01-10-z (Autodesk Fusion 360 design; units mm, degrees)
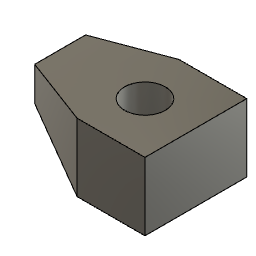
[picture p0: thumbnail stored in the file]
sketch "スケッチ1" plane through (0, 0, 0) normal (0, 0, 1) x axis (1, 0, 0)
  line L1 (-40, 0) -> (0, 0)
  line L2 (-40, 20) -> (-40, 0)
  line L3 (0, 20) -> (-40, 20)
  line L4 (0, 0) -> (0, 20)
  point P1 (0, 0)
  point P2 (0, 0)
  point P5 (0, 20)
  point P4 (-40, 20)
  horizontal L1
  vertical L2
  horizontal L3
  vertical L4
  coincident P1 P2
  dimension "d1" distance P2 P5 = 20
  dimension "d2" distance P4 P5 = 40
extrude "押し出し1" new body sketch "スケッチ1" distance 30
sketch "スケッチ2" plane through (0, 20, 0) normal (0, 1, 0) x axis (-1, 0, 0)
  line L1 (40, 15) -> (40, -15)
  line L2 (0, 15) -> (40, 15)
  line L3 (0, -15) -> (0, 15)
  line L4 (40, -15) -> (0, -15)
  line L5 (0, -15) -> (20, -15)
  line L6 (0, 15) -> (0, -15)
  line L7 (40, -7.5) -> (40, 7.5)
  line L8 (20, -15) -> (40, -7.5)
  line L9 (20, 15) -> (0, 15)
  line L10 (40, 7.5) -> (20, 15)
  point P6 (20, -15)
  point P7 (0, -15)
  point P9 (40, 7.5)
  point P10 (40, -7.5)
  parallel L4 L5
  perpendicular L4 L6
  perpendicular L2 L7
  perpendicular L6 L9
  equal L8 L10
  equal L5 L9
  collinear L4 L5
  collinear L3 L6
  collinear L2 L9
  collinear L1 L7
  dimension "d5" distance P6 P7 = 20
  dimension "d6" distance P9 P10 = 15
extrude "押し出し2" sketch "スケッチ2" no distance stored
sketch "スケッチ3" plane through (0, 0, 0) normal (0, 0, 1) x axis (1, 0, 0)
  line L1 (-20, 0) -> (-40, 10)
  line L2 (-40, 0) -> (-20, 0)
  line L3 (-40, 10) -> (-40, 0)
  line L4 (-20, 0) -> (-40, 0)
  line L5 (-40, 0) -> (-40, 20)
  line L6 (-40, 20) -> (-20, 20)
  line L7 (0, 20) -> (0, 0)
  point P2 (-40, 10)
  point P3 (-20, 0)
  horizontal L2
  collinear L2 L4
  collinear L3 L5
  dimension "d8" distance P2 L6 = 10
  dimension "d9" distance P3 L7 = 20
extrude "押し出し3" cut sketch "スケッチ3" profile of L1 L2 L3 L4 L5 no distance stored
sketch "スケッチ4" plane through (0, 20, 0) normal (0, 1, 0) x axis (-1, 0, 0)
  line L1 (40, -7.5) -> (20, -15)
  line L2 (40, 7.5) -> (40, -7.5)
  line L3 (20, 15) -> (40, 7.5)
  line L4 (0, 15) -> (20, 15)
  line L5 (0, -15) -> (0, 15)
  line L6 (20, -15) -> (0, -15)
  circle C1 centre (15, 0) radius 6
  point P1 (0, 0)
  point P8 (15, 0)
  horizontal P1 P8
  dimension "d11" distance L5 P8 = 15
  dimension "d12" diameter C1 = 12
extrude "押し出し4" cut sketch "スケッチ4" profile of C1 no distance stored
